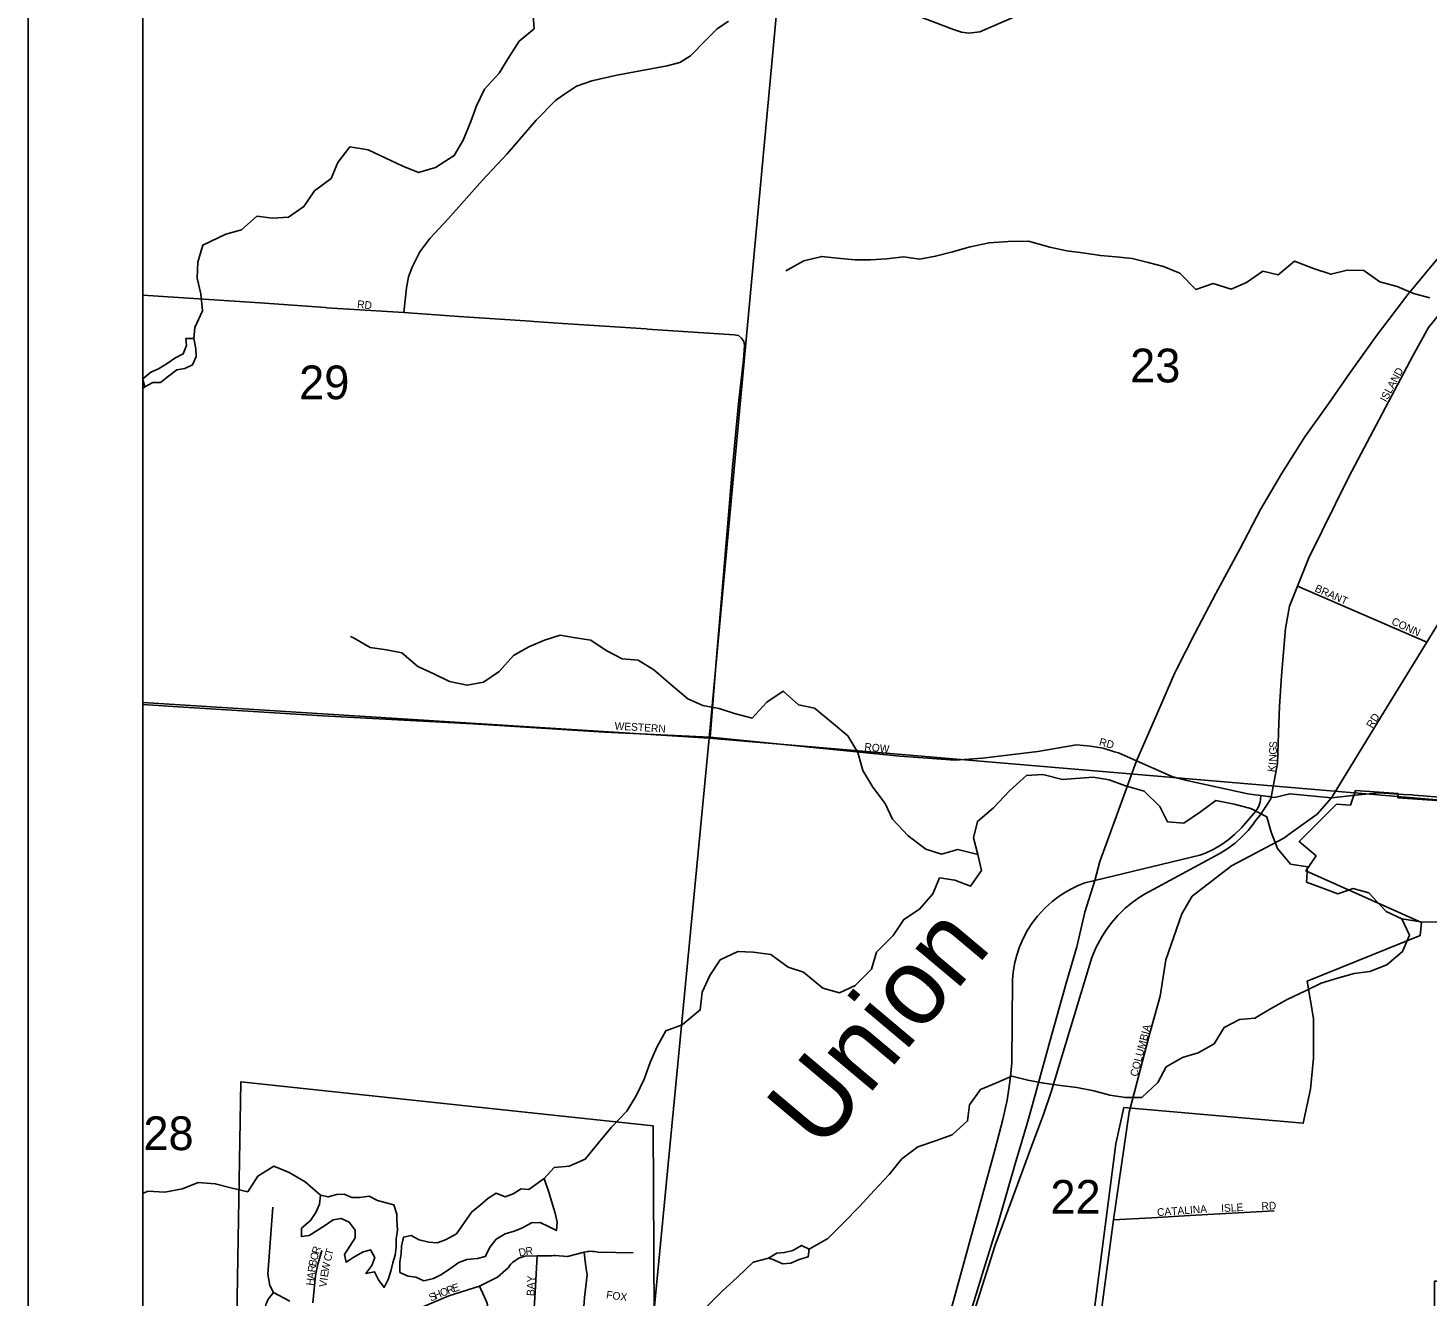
# Model space of a CAD drawing. Extents: x 0 to 34, y -4 to 22.
# Drawn here: x 2 to 3.221, y 15.668 to 16.774 of the extents above; entities that cross this region are included whole.
import ezdxf

# ---------------------------------------------------------------- set-up
doc = ezdxf.new("R2010")
doc.units = 0
for name, color, linetype in [('GM_P_County_Alignment', 7, 'Continuous'), ('GM_X_City_Street', 7, 'Continuous'), ('GM_X_City_Street_Text', 7, 'Continuous'), ('GM_X_Corporation', 7, 'Continuous'), ('GM_X_County_Road', 7, 'Continuous'), ('GM_X_Interchange_Ramps', 7, 'Continuous'), ('GM_X_Interstate_Route', 7, 'Continuous'), ('GM_X_Minor_Lake', 7, 'Continuous'), ('GM_X_Minor_River', 7, 'Continuous'), ('GM_X_Minor_River_Text', 7, 'Continuous'), ('GM_X_Section', 7, 'Continuous'), ('GM_X_Section_Text', 7, 'Continuous'), ('GM_X_Township_Road', 7, 'Continuous'), ('GM_X_Township_Subdivision', 7, 'Continuous'), ('GM_X_Township_Subdivision_Text', 7, 'Continuous'), ('SH_Data', 7, 'Continuous'), ('SN_P_Text', 7, 'Continuous')]:
    doc.layers.add(name, color=color, linetype=linetype)

msp = doc.modelspace()

# ---------------------------------------------------------------- linework, layer by layer
at = {"layer": 'GM_P_County_Alignment'}
msp.add_lwpolyline([(2.3277, 16.5257), (2.3299, 16.5472), (2.3318, 16.5569), (2.3348, 16.5654), (2.3416, 16.5787), (2.3502, 16.5903), (2.3662, 16.6073), (2.3964, 16.641), (2.4177, 16.664), (2.4431, 16.6933), (2.46, 16.7105), (2.4669, 16.7156), (2.4782, 16.723), (2.4917, 16.7278), (2.5135, 16.7326), (2.5573, 16.7407), (2.5684, 16.7438), (2.5776, 16.7495), (2.591, 16.7631), (2.601, 16.773), (2.6106, 16.7797)], dxfattribs=at)
at = {"layer": 'GM_X_City_Street'}
for points in [[(2.7647, 16.7885), (2.8069, 16.7725), (2.814, 16.7701), (2.8205, 16.7694), (2.8298, 16.7705), (2.8601, 16.7836)], [(3.0904, 16.1595), (3.0911, 16.1824), (3.0929, 16.2089), (3.0964, 16.2503), (3.0999, 16.2697), (3.1068, 16.2871), (3.1168, 16.3119), (3.1516, 16.3824), (3.2074, 16.488), (3.2209, 16.5128), (3.2475, 16.5451), (3.325, 16.6415), (3.4062, 16.7388)], [(2.1, 16.5409), (2.1313, 16.5388), (2.2066, 16.5339), (2.2595, 16.53)], [(2.2595, 16.53), (2.2606, 16.5299), (2.3277, 16.5257), (2.3756, 16.5222), (2.4381, 16.5181), (2.4411, 16.5179)], [(2.4411, 16.5179), (2.4663, 16.5161), (2.5389, 16.5114)], [(2.5389, 16.5114), (2.54, 16.5113), (2.6157, 16.5062), (2.6194, 16.5056), (2.6222, 16.5034), (2.6241, 16.5004), (2.6246, 16.4969), (2.6238, 16.4844), (2.6196, 16.4464), (2.6142, 16.391), (2.6051, 16.2835), (2.6002, 16.2248), (2.5947, 16.1555)], [(3.1068, 16.2871), (3.2195, 16.2382)], [(3.1365, 16.1027), (3.1798, 16.1734), (3.2195, 16.2382), (3.2298, 16.255)], [(2.9473, 16.1428), (2.9375, 16.146), (2.9263, 16.1477), (2.9141, 16.1487), (2.8804, 16.1431), (2.8323, 16.1371), (2.8082, 16.1354), (2.7601, 16.1389), (2.5947, 16.1555), (2.5026, 16.1599), (2.3878, 16.1671), (2.2567, 16.1742), (2.1266, 16.1823), (2.1, 16.184)], [(3.0839, 16.1033), (3.0895, 16.1324), (3.0904, 16.1591), (3.0904, 16.1595)], [(2.9666, 16.1348), (2.9508, 16.1417), (2.9473, 16.1428)], [(2.9942, 16.1226), (2.9666, 16.1348)], [(3.0676, 16.1056), (3.0635, 16.1062), (3.0104, 16.1178), (2.9981, 16.1209), (2.9942, 16.1226)], [(3.0819, 16.1036), (3.0811, 16.1037), (3.075, 16.1045), (3.0676, 16.1056)], [(3.1365, 16.1027), (3.1, 16.1062), (3.0867, 16.1029), (3.0839, 16.1033), (3.0819, 16.1036)], [(3.0996, 16.0709), (3.1241, 16.0884), (3.1365, 16.1027)], [(3.1574, 16.1049), (3.1365, 16.1027)], [(2.9645, 15.8452), (2.9772, 15.8943), (2.987, 15.9296), (2.9919, 15.9613), (3.0059, 16.0014), (3.0151, 16.0167), (3.0493, 16.0433), (3.0949, 16.0675), (3.0995, 16.0708), (3.0996, 16.0709)], [(2.9465, 15.7345), (2.9798, 15.7364), (2.9798, 15.7364)], [(2.9798, 15.7364), (3.0131, 15.7383), (3.0131, 15.7383)], [(3.0131, 15.7383), (3.0864, 15.7425)]]:
    msp.add_lwpolyline(points, dxfattribs=at)
at = {"layer": 'GM_X_Corporation'}
for points in [[(3.3793, 18.4047), (3.1873, 18.408), (3.1887, 18.4667), (3.165, 18.4667), (3.1862, 18.4829), (3.1889, 18.8429), (3.1489, 18.8496), (3.1489, 18.8896), (3.0902, 18.8962), (3.0902, 18.8696), (2.9995, 18.8796), (2.9995, 18.8476), (2.866, 18.858), (2.8473, 18.8608), (2.85, 18.9128), (2.8529, 18.9403), (2.6804, 18.9614), (2.6503, 18.6171), (2.4764, 18.6232), (2.4729, 18.5238), (2.4405, 18.5003), (2.4368, 18.2868), (2.1, 18.3167), (2.1, 14.8755)], [(2.9223, 15.599), (2.9485, 15.801), (2.9553, 15.8325), (3.1118, 15.8189), (3.1181, 15.8486), (3.1209, 15.8756), (3.1209, 15.9101), (3.1152, 15.9427), (3.2139, 15.9826), (3.2149, 15.9939), (3.1141, 16.0388), (3.1231, 16.0521), (3.1084, 16.0645), (3.1409, 16.097), (3.1529, 16.0962), (3.1573, 16.1089), (3.1945, 16.1063), (3.1943, 16.1026), (3.2577, 16.0981)], [(2.1794, 15.4954), (2.1856, 15.8551), (2.545, 15.8167), (2.547, 15.4302)]]:
    msp.add_lwpolyline(points, dxfattribs=at)
at = {"layer": 'GM_X_County_Road'}
msp.add_lwpolyline([(2.9327, 15.6295), (2.9331, 15.6317), (2.9354, 15.6518), (2.9465, 15.7345), (2.9602, 15.8286), (2.9645, 15.8452)], dxfattribs=at)
at = {"layer": 'GM_X_Interchange_Ramps'}
for points in [[(3.075, 16.1045), (3.0746, 16.1012), (3.0743, 16.0988), (3.0735, 16.0961), (3.0721, 16.0936), (3.0702, 16.0907), (3.0631, 16.0825), (3.0579, 16.0763), (3.052, 16.0705), (3.0461, 16.0656), (3.0403, 16.0616), (3.034, 16.0579), (3.0265, 16.0544), (3.0216, 16.0525), (2.9302, 16.0305), (2.9215, 16.0284), (2.9157, 16.0261), (2.9097, 16.0233), (2.9046, 16.0204), (2.8989, 16.0168), (2.8929, 16.0122), (2.8865, 16.0065), (2.8801, 15.9995), (2.8758, 15.9938), (2.8715, 15.9873), (2.8676, 15.98), (2.8644, 15.9726), (2.862, 15.9655), (2.8604, 15.9591), (2.8589, 15.9505), (2.8583, 15.9438), (2.8577, 15.8716), (2.857, 15.8624), (2.8561, 15.855), (2.855, 15.8469), (2.8536, 15.8389), (2.8518, 15.8301), (2.8499, 15.8221), (2.8429, 15.7954), (2.7975, 15.6304)], [(2.8152, 15.6244), (2.8431, 15.7126), (2.8762, 15.8019), (2.8855, 15.8266), (2.8922, 15.8462), (2.9276, 15.9633), (2.9314, 15.9724), (2.9359, 15.9808), (2.9397, 15.9868), (2.9448, 15.9937), (2.9502, 15.9999), (2.9567, 16.0063), (2.9623, 16.0109), (2.9688, 16.0156), (2.9741, 16.0189), (3.0386, 16.0538), (3.0451, 16.0578), (3.0524, 16.0632), (3.0583, 16.0685), (3.0638, 16.0742), (3.0683, 16.0797), (3.0709, 16.0833), (3.0742, 16.0875), (3.0775, 16.0923), (3.0797, 16.0958), (3.0837, 16.1016), (3.0839, 16.1033)]]:
    msp.add_lwpolyline(points, dxfattribs=at)
at = {"layer": 'GM_X_Interstate_Route'}
for points in [[(3, 16.2115), (3.0013, 16.2145), (3.0174, 16.2459), (3.0356, 16.2808), (3.0567, 16.3201), (3.0747, 16.354), (3.0928, 16.3851), (3.1132, 16.4174), (3.1343, 16.4471), (3.1521, 16.4726), (3.1754, 16.505), (3.2031, 16.5413), (3.2301, 16.574), (3.2662, 16.6193), (3.2933, 16.6514), (3.3282, 16.6947), (3.3609, 16.7345), (3.3893, 16.7694)], [(2.925, 16.014), (2.9302, 16.0305), (2.9345, 16.047), (2.95, 16.0893), (2.9666, 16.1348), (2.9819, 16.1701), (3, 16.2115)], [(2.8641, 15.7952), (2.871, 15.8185), (2.8756, 15.834), (2.8908, 15.89), (2.9051, 15.9411), (2.9143, 15.9726), (2.9215, 16.0029), (2.925, 16.014)], [(2.736, 15.4207), (2.7488, 15.4492), (2.7643, 15.4885), (2.7815, 15.5352), (2.798, 15.5806), (2.813, 15.6251), (2.8319, 15.687), (2.846, 15.733), (2.8612, 15.7854), (2.8641, 15.7952)]]:
    msp.add_lwpolyline(points, dxfattribs=at)
at = {"layer": 'GM_X_Minor_Lake'}
for points in [[(2.1213, 16.4813), (2.1137, 16.4767), (2.107, 16.4738), (2.1002, 16.4678), (2.1019, 16.4608), (2.1089, 16.4647), (2.1156, 16.4648), (2.1224, 16.4701), (2.1297, 16.4758), (2.1367, 16.477), (2.1435, 16.4801), (2.1465, 16.4873), (2.1464, 16.494), (2.1447, 16.5032)], [(2.1377, 16.503), (2.1382, 16.4971), (2.1354, 16.4897), (2.1281, 16.486), (2.1213, 16.4813)], [(2.1447, 16.5032), (2.1377, 16.503)], [(2.4501, 15.7708), (2.4366, 15.761), (2.4299, 15.7618), (2.423, 15.7573), (2.416, 15.7546), (2.4083, 15.7578), (2.4008, 15.7533), (2.3938, 15.7471), (2.3871, 15.7415), (2.3735, 15.7225), (2.3641, 15.7172), (2.3566, 15.7145), (2.3494, 15.7153), (2.3409, 15.7172), (2.3342, 15.7209), (2.3275, 15.7196), (2.3256, 15.7118), (2.3253, 15.7051), (2.3243, 15.6979), (2.3243, 15.6888), (2.3315, 15.6854), (2.3382, 15.6846), (2.3451, 15.6814), (2.3534, 15.6835), (2.3604, 15.687), (2.3679, 15.692), (2.3757, 15.6975)], [(2.3757, 15.6975), (2.3826, 15.7001), (2.392, 15.7009), (2.3986, 15.7027), (2.4029, 15.711), (2.4083, 15.7177), (2.416, 15.7223), (2.4238, 15.7247), (2.4305, 15.7273), (2.439, 15.7321), (2.4465, 15.7324), (2.4537, 15.7289), (2.4607, 15.7252), (2.4615, 15.7327), (2.4596, 15.7404), (2.4572, 15.7479), (2.454, 15.7589), (2.4501, 15.7708)], [(2.255, 15.7562), (2.2542, 15.7484), (2.251, 15.741), (2.2462, 15.734), (2.2384, 15.7273), (2.2384, 15.7201), (2.2451, 15.7209), (2.2585, 15.7295), (2.266, 15.7345), (2.2729, 15.7359), (2.2799, 15.7327), (2.2852, 15.7257), (2.2852, 15.719), (2.2807, 15.7116), (2.2759, 15.7043), (2.2775, 15.6977), (2.2841, 15.7022), (2.2916, 15.7065), (2.2986, 15.7086), (2.3023, 15.7019), (2.2997, 15.6947), (2.2946, 15.6878), (2.3021, 15.6894), (2.3056, 15.6824), (2.3104, 15.6757), (2.3141, 15.6827), (2.3163, 15.6899), (2.3181, 15.6971), (2.32, 15.7038), (2.3211, 15.7108), (2.3211, 15.7182), (2.3221, 15.7257), (2.3216, 15.7345)], [(2.3216, 15.7345), (2.3216, 15.7396), (2.3189, 15.7476), (2.3122, 15.7495), (2.3047, 15.7514), (2.2975, 15.7554), (2.2892, 15.7541), (2.2823, 15.7541), (2.2756, 15.757), (2.2689, 15.7567), (2.2617, 15.7546), (2.255, 15.7562)], [(2.6723, 15.7001), (2.6803, 15.7025), (2.6811, 15.7092), (2.6744, 15.7124), (2.6669, 15.7078), (2.6597, 15.7062), (2.6528, 15.7057), (2.6455, 15.7011)], [(2.6455, 15.7011), (2.6488, 15.7003), (2.6581, 15.6963), (2.6651, 15.6969), (2.6723, 15.7001)]]:
    msp.add_lwpolyline(points, dxfattribs=at)
at = {"layer": 'GM_X_Minor_River'}
msp.add_line((2.1019, 16.4608), (2.1, 16.4594), dxfattribs=at)
for points in [[(2.4401, 16.7878), (2.4414, 16.7731), (2.4281, 16.7622), (2.4195, 16.7488), (2.4109, 16.7344), (2.3981, 16.7205), (2.3909, 16.7058), (2.3861, 16.6924), (2.3794, 16.6759), (2.3716, 16.6625), (2.3553, 16.6521), (2.3406, 16.6478), (2.3267, 16.6534), (2.312, 16.6604), (2.2967, 16.6676), (2.2807, 16.6703), (2.2702, 16.6564), (2.2643, 16.6427), (2.2499, 16.6318), (2.2405, 16.6181), (2.2272, 16.6088), (2.2132, 16.608), (2.1996, 16.6096), (2.1862, 16.5978), (2.1726, 16.5941), (2.1523, 16.5845), (2.1482, 16.5695), (2.1474, 16.5556), (2.1506, 16.542), (2.152, 16.5273), (2.1456, 16.5128), (2.1447, 16.5032)], [(3.2223, 16.5385), (3.2081, 16.5422), (3.1937, 16.5484), (3.1787, 16.5526), (3.1648, 16.5625), (3.1501, 16.5628), (3.1359, 16.5591), (3.1209, 16.5641), (3.1043, 16.5705), (3.0899, 16.5585), (3.0765, 16.5617), (3.0623, 16.5518), (3.0489, 16.5462), (3.0332, 16.551), (3.0182, 16.5457), (3.0043, 16.5601), (2.9901, 16.566), (2.9765, 16.5692), (2.9628, 16.5727), (2.9484, 16.5743), (2.935, 16.5754), (2.9213, 16.5775), (2.9058, 16.5794), (2.8908, 16.5828), (2.8724, 16.5879), (2.8545, 16.5877), (2.8379, 16.5866), (2.8213, 16.5831), (2.806, 16.5786), (2.7913, 16.5748), (2.7772, 16.5722), (2.7635, 16.5743), (2.7485, 16.5724), (2.7346, 16.5716), (2.7212, 16.5716), (2.7055, 16.573), (2.6921, 16.5746), (2.6763, 16.5708), (2.6613, 16.5625), (2.6608, 16.562)], [(2.8282, 16.0531), (2.8108, 16.0574), (2.7964, 16.0534), (2.7828, 16.0577), (2.7675, 16.0694), (2.7536, 16.0839), (2.7472, 16.0975), (2.7367, 16.1119), (2.7279, 16.1264), (2.7234, 16.1421), (2.7148, 16.1566), (2.7006, 16.1686), (2.6857, 16.1809), (2.6717, 16.1838), (2.6584, 16.1956), (2.6442, 16.186), (2.6313, 16.1721), (2.6161, 16.1761), (2.6025, 16.1804), (2.5885, 16.183), (2.5752, 16.1889), (2.5605, 16.2015), (2.5455, 16.2143), (2.5321, 16.2226), (2.5179, 16.2237), (2.504, 16.2311), (2.4906, 16.24), (2.4773, 16.2421), (2.4639, 16.2445), (2.4502, 16.24), (2.4366, 16.2341), (2.4232, 16.2266), (2.4109, 16.2127), (2.397, 16.2033), (2.3828, 16.2007), (2.3676, 16.2039), (2.3537, 16.2106), (2.3398, 16.217), (2.3259, 16.229), (2.3125, 16.2317), (2.2983, 16.2338), (2.2839, 16.2421), (2.2812, 16.2432)], [(3.2295, 15.9941), (3.2145, 15.9946), (3.1977, 15.997), (3.184, 16.0034), (3.169, 16.0197), (3.1554, 16.0235), (3.142, 16.0189), (3.1281, 16.024), (3.1147, 16.0291), (3.1155, 16.0424), (3.1008, 16.0448), (3.0893, 16.0585), (3.084, 16.0726), (3.0802, 16.086), (3.0661, 16.0932), (3.0516, 16.0972), (3.0356, 16.1002), (3.0222, 16.0903), (3.0077, 16.0804), (2.9936, 16.0817), (2.9869, 16.0951), (2.973, 16.1084), (2.9569, 16.113), (2.9425, 16.1183), (2.9286, 16.1207), (2.9018, 16.1186), (2.8847, 16.1229), (2.8705, 16.1221), (2.8558, 16.1087), (2.8419, 16.094), (2.8277, 16.082), (2.8242, 16.0676), (2.8282, 16.0531), (2.8314, 16.0392), (2.8218, 16.0256), (2.8082, 16.0307), (2.7948, 16.0328), (2.7889, 16.0189), (2.7774, 16.0056), (2.7635, 15.9965), (2.7544, 15.9826)], [(3.1977, 15.997), (3.2044, 15.9828), (3.1985, 15.9687), (3.1846, 15.9569), (3.1699, 15.9513), (3.1562, 15.9494), (3.1418, 15.9454), (3.1276, 15.9409), (3.1137, 15.9342), (3.0979, 15.9267), (3.0834, 15.9187), (3.0695, 15.9104), (3.0562, 15.9093), (3.0428, 15.9024), (3.0342, 15.8882), (3.0203, 15.8802), (3.0067, 15.8762), (2.9922, 15.8679), (2.985, 15.8543), (2.9711, 15.8412), (2.9569, 15.8412), (2.9433, 15.8433), (2.9294, 15.8471), (2.9144, 15.85), (2.9002, 15.8519), (2.8858, 15.8537), (2.8716, 15.8564), (2.8579, 15.8599), (2.8443, 15.854), (2.8304, 15.8484), (2.8208, 15.8348), (2.8192, 15.8209), (2.8058, 15.8088), (2.7911, 15.8035), (2.7758, 15.7984), (2.7619, 15.7877), (2.7507, 15.7741), (2.7376, 15.7602), (2.7253, 15.7466), (2.7111, 15.7321), (2.6972, 15.7185), (2.6811, 15.7092)], [(2.7544, 15.9826), (2.7397, 15.9679), (2.7354, 15.9532), (2.7212, 15.939), (2.7076, 15.9326), (2.6929, 15.9366), (2.676, 15.9505), (2.6627, 15.9548), (2.6477, 15.966), (2.6322, 15.9679), (2.6188, 15.9687), (2.6035, 15.9612), (2.5944, 15.9478), (2.5878, 15.9331), (2.5861, 15.9176), (2.5704, 15.9048), (2.5562, 15.8995), (2.5484, 15.8853), (2.5425, 15.8717), (2.5372, 15.8572), (2.5305, 15.8433), (2.5222, 15.8294), (2.5086, 15.8153), (2.4973, 15.8019), (2.4858, 15.7875), (2.4719, 15.7813), (2.4586, 15.7802), (2.4501, 15.7708)], [(2.255, 15.7562), (2.2416, 15.7677), (2.2277, 15.776), (2.2143, 15.7813), (2.2004, 15.7728), (2.1916, 15.7591), (2.1779, 15.7623), (2.1632, 15.7661), (2.1483, 15.7672), (2.1346, 15.7618), (2.1194, 15.7589), (2.1046, 15.7597), (2.1, 15.7577)], [(2.6455, 15.7011), (2.6322, 15.6977), (2.6185, 15.6846), (2.6052, 15.6723), (2.5912, 15.6586), (2.5773, 15.6455), (2.5629, 15.6418), (2.549, 15.6303), (2.5343, 15.625), (2.5201, 15.6215), (2.5123, 15.6183)]]:
    msp.add_lwpolyline(points, dxfattribs=at)
at = {"layer": 'GM_X_Section'}
for points in [[(2.1, 16.8931), (2.1, 16.1858), (2.5939, 16.1545), (2.6586, 16.8529)], [(2.662, 16.8858), (3.377, 16.8184), (3.3036, 16.0944), (2.5939, 16.1545), (2.6586, 16.8529)], [(2.1, 16.1858), (2.1, 15.4645), (2.5242, 15.4299), (2.5939, 16.1545)], [(3.264, 15.6812), (3.3036, 16.0944), (2.5939, 16.1545), (2.5242, 15.4299), (3.2264, 15.3757), (3.2264, 15.6812)]]:
    msp.add_lwpolyline(points, close=True, dxfattribs=at)
at = {"layer": 'GM_X_Township_Road'}
for points in [[(3.1991, 16.1056), (3.1779, 16.107), (3.1574, 16.1049)], [(3.2061, 16.1052), (3.1991, 16.1056)], [(3.3096, 16.0687), (3.3095, 16.0709), (3.3054, 16.0902), (3.3003, 16.0978), (3.2802, 16.0995), (3.2083, 16.105), (3.2061, 16.1052)]]:
    msp.add_lwpolyline(points, dxfattribs=at)
at = {"layer": 'GM_X_Township_Subdivision'}
for points in [[(2.2136, 15.7457), (2.209, 15.6872), (2.2107, 15.6773), (2.214, 15.6713), (2.2282, 15.6637)], [(2.2484, 15.6624), (2.2507, 15.6862), (2.2527, 15.6961), (2.2563, 15.708)], [(2.3422, 15.658), (2.367, 15.6685), (2.3935, 15.6768), (2.4092, 15.6847), (2.4189, 15.6932), (2.4198, 15.6944), (2.4211, 15.6959), (2.4224, 15.6973), (2.4236, 15.6983), (2.4249, 15.6992), (2.4264, 15.7002), (2.428, 15.7011), (2.4298, 15.7019), (2.4313, 15.7024), (2.4324, 15.7027), (2.4334, 15.7029), (2.444, 15.7032), (2.4547, 15.7033), (2.4565, 15.7033), (2.4582, 15.7034), (2.459, 15.7035), (2.4596, 15.7036), (2.4705, 15.7028), (2.4849, 15.7064), (2.4874, 15.7069), (2.4891, 15.7071), (2.4909, 15.7072), (2.4922, 15.7071), (2.4939, 15.707), (2.497, 15.7063), (2.5276, 15.7058)], [(2.4682, 15.4697), (2.4242, 15.4726), (2.4301, 15.5301), (2.4338, 15.5387), (2.4447, 15.5489), (2.4576, 15.5633), (2.4698, 15.5726), (2.4757, 15.5855), (2.4827, 15.6314), (2.4853, 15.6668), (2.4876, 15.6866), (2.4867, 15.6919), (2.4857, 15.6985), (2.4849, 15.7064)], [(2.4374, 15.6326), (2.4404, 15.6466), (2.4419, 15.6663), (2.444, 15.7032)], [(2.3855, 15.5657), (2.3819, 15.5713), (2.3815, 15.5789), (2.3832, 15.6014), (2.3858, 15.6127), (2.3951, 15.6256), (2.3987, 15.6381), (2.4011, 15.6539), (2.4011, 15.6564), (2.4009, 15.6586), (2.4005, 15.6605), (2.4, 15.6625), (2.3995, 15.6639), (2.3935, 15.6768)], [(2.2004, 15.5841), (2.2065, 15.6537), (2.2068, 15.6574), (2.2075, 15.6607), (2.2082, 15.6626), (2.2092, 15.6648), (2.2105, 15.6669), (2.2116, 15.6684), (2.214, 15.6713)]]:
    msp.add_lwpolyline(points, dxfattribs=at)
at = {"layer": 'SH_Data'}
for p, q in [((2, 21), (2, 14)), ((2.1, 20.9), (2.1, 14.1))]:
    msp.add_line(p, q, dxfattribs=at)
at = {"layer": 'SN_P_Text'}
msp.add_lwpolyline([(8.9, 14.1), (8.9, 20.9), (2.1, 20.9), (2.1, 14.1)], close=True, dxfattribs=at)

# ---------------------------------------------------------------- texts
at = {"layer": 'GM_X_City_Street_Text'}
for s, rotation, p in [('RD', 353.9934, (2.2867, 16.5299)), ('ISLAND', 61.7587, (3.1842, 16.4471)), ('BRANT', 336.1659, (3.1213, 16.2828)), ('CONN', 335.4343, (3.1882, 16.2541)), ('RD', 57.9872, (3.172, 16.1627)), ('WESTERN', 356.5303, (2.5113, 16.1621)), ('ROW', 354.5626, (2.729, 16.1439)), ('RD', 345.2688, (2.9334, 16.1485)), ('S', 88.251, (3.0889, 16.1459)), ('N', 87.8424, (3.0885, 16.1341)), ('G', 88.2701, (3.0887, 16.1401)), ('K', 81.7524, (3.0873, 16.1247)), ('I', 84.8522, (3.0882, 16.1309)), ('COLUMBIA', 75.0182, (2.9671, 15.859)), ('CATALINA', 4.0302, (2.9846, 15.7379)), ('ISLE', 2.9398, (3.0404, 15.7414)), ('RD', 3.1778, (3.0756, 15.7432))]:
    msp.add_text(s, height=0.00667, rotation=rotation, dxfattribs=at).set_placement(p)
at = {"layer": 'GM_X_Minor_River_Text'}
msp.add_text('Union', height=0.06666, rotation=49.9472, dxfattribs=at).set_placement((2.691, 15.7933))
at = {"layer": 'GM_X_Section_Text'}
for s, p in [('23', (2.9609, 16.4648)), ('29', (2.2364, 16.4501)), ('28', (2.1006, 15.7954)), ('22', (2.8914, 15.7399))]:
    msp.add_text(s, height=0.02944, rotation=0, dxfattribs=at).set_placement(p)
at = {"layer": 'GM_X_Township_Subdivision_Text'}
for s, rotation, p in [('R', 73.731, (2.2536, 15.7044)), ('T', 73.6644, (2.2652, 15.703)), ('D', 12.9176, (2.4286, 15.7026)), ('R', 5.6913, (2.4341, 15.7039)), ('B', 78.5567, (2.251, 15.6937)), ('O', 74.0126, (2.252, 15.6988)), ('W', 79.0033, (2.2621, 15.6888)), ('C', 75.0686, (2.2639, 15.6979)), ('A', 82.9888, (2.2497, 15.6828)), ('R', 83.0202, (2.2504, 15.6886)), ('E', 81.8042, (2.2614, 15.6843)), ('BAY', 88.0261, (2.4414, 15.6681)), ('H', 83.0105, (2.249, 15.677)), ('V', 83.0756, (2.2603, 15.6756)), ('I', 82.8099, (2.261, 15.6814)), ('H', 22.8891, (2.3555, 15.6651)), ('O', 22.4063, (2.3609, 15.6674)), ('R', 19.925, (2.3663, 15.6696)), ('E', 19.1263, (2.3712, 15.6714)), ('FOX', 351.8666, (2.5038, 15.6663)), ('S', 22.8721, (2.3512, 15.6633))]:
    msp.add_text(s, height=0.00667, rotation=rotation, dxfattribs=at).set_placement(p)

doc.saveas('drawing.dxf')
